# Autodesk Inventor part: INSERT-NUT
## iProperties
Created: 2007-09
Part Number: INSERT-NUT
Material: Brass, Soft Yellow
Document SubType Name: Modeling
Density: 8.47 g/cm^3
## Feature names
1. Base1
2. Extrusion1
3. Hole1
